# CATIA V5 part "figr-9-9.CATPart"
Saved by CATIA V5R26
Part number: Part1
Bounding box of the stored display mesh (mm): x -15.705 to 88.369, y 0 to 286.83, z -20.723 to 20.723
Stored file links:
  D:\_Deepak\CATIA\CATIA V5-6R2016_Deepak\Resources\Part files\Partfiles\c09_catia_v5_6r2016_prt\figr-9-9.CATPart
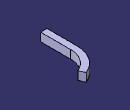
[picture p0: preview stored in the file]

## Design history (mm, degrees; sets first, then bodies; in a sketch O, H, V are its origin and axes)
Body1 (main body)
  Sketch1 on xy-plane, origin (0, 0, 0), H (1, 0, 0), V (0, 1, 0)
    line L1 (0, 0) -> (0, 150)
    arc A1 centre (131.8599, 150) radius 131.8599 from (0, 150) to (82.4884, 272.2681) cw
    length L1 = 150
    tangency: A1 L1
  Sketch2 on zx-plane, origin (0, 0, 0), H (-1, 0, 0), V (0, 0, 1)
    line L1 (15.7048, 20.7231) -> (15.7048, -20.7231)
    line L2 (15.7048, -20.7231) -> (-15.7048, -20.7231)
    line L3 (-15.7048, -20.7231) -> (-15.7048, 20.7231)
    line L4 (-15.7048, 20.7231) -> (15.7048, 20.7231)
    vertical: L1 V, L3 V
    horizontal: L2 H, L4 H
    equidistance: L1 L3 O, L2 L4 O
  Rib1: profile Sketch2, centre curve Sketch1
